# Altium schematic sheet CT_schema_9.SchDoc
size 308 x 210 mm
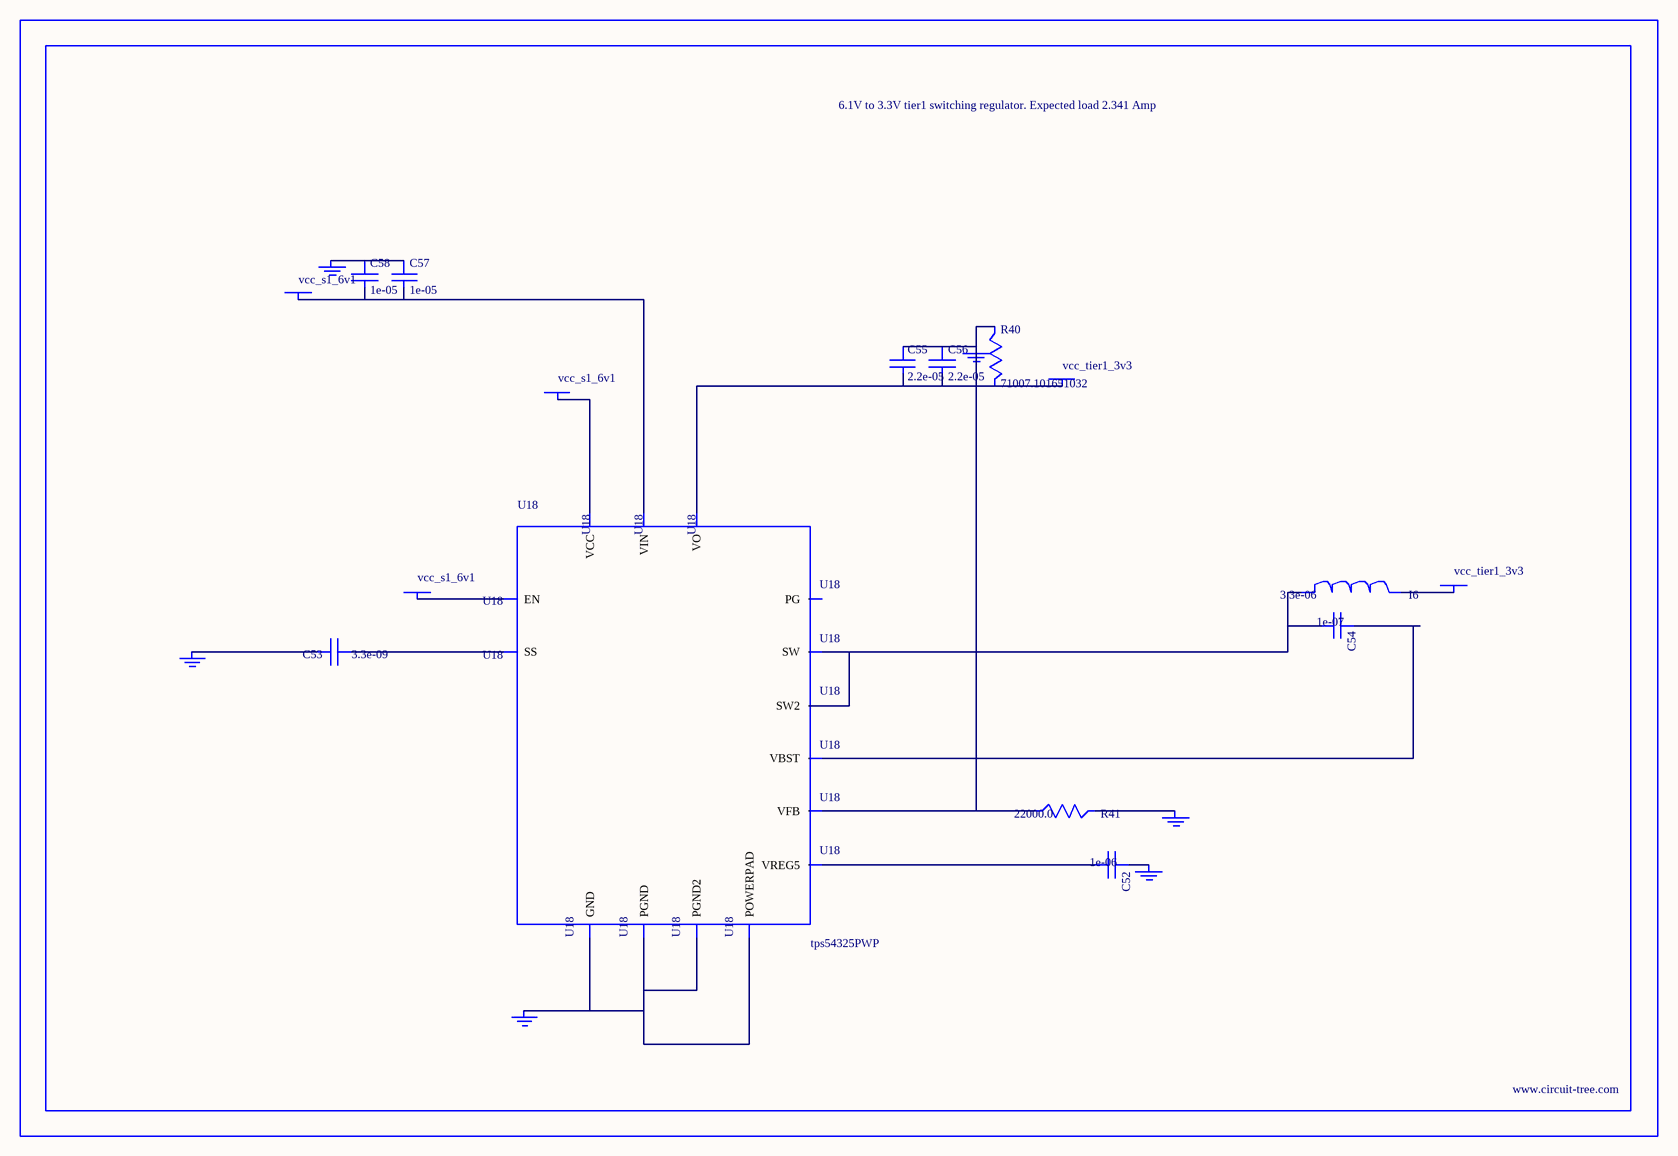
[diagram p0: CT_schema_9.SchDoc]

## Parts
BORDER8  (no value)
C52  1e-06  [C0603]
C53  3.3e-09  [C0402]
C54  1e-07  [C0402]
C55  2.2e-05  [C1210]
C56  2.2e-05  [C1210]
C57  1e-05  [C0805]
C58  1e-05  [C0805]
GND_INSTANCE_8_0  (no value)
GND_INSTANCE_8_1  (no value)
GND_INSTANCE_8_2  (no value)
GND_INSTANCE_8_3  (no value)
GND_INSTANCE_8_4  (no value)
GND_INSTANCE_8_5  (no value)
I6  3.3e-06  [WE-HCI_7030/7040/7050]
POWER_INSTANCE_8_0  vcc_tier1_3v3
POWER_INSTANCE_8_1  vcc_s1_6v1
POWER_INSTANCE_8_2  vcc_tier1_3v3
POWER_INSTANCE_8_3  vcc_s1_6v1
POWER_INSTANCE_8_4  vcc_s1_6v1
R40  71007.101651032  [R0603]
R41  22000.0  [R0603]
U18  tps54325PWP  [HTSSOP14]

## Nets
NetC52_1: C52.1 GND_INSTANCE_8_2.0(GND)
NetC52_2: C52.2 U18.3(VREG5)
NetC53_1: C53.1 U18.4(SS)
NetC53_2: C53.2 GND_INSTANCE_8_3.0(GND)
NetC54_1: C54.1 U18.12(VBST)
NetC54_2: C54.2 I6.1 U18.10(SW) U18.11(SW2)
NetC55_1: C55.1 C56.1 GND_INSTANCE_8_0.0(GND) R40.1 R41.1 U18.2(VFB)
NetC55_2: C55.2 C56.2 POWER_INSTANCE_8_0.0(PWR) R40.2 U18.1(VO)
NetC57_1: C57.1 C58.1 GND_INSTANCE_8_5.0(GND)
NetC57_2: C57.2 C58.2 POWER_INSTANCE_8_3.0(PWR) U18.13(VIN)
NetGND_INSTANCE_8_1_0: GND_INSTANCE_8_1.0(GND) R41.2
NetGND_INSTANCE_8_4_0: GND_INSTANCE_8_4.0(GND) U18.5(GND) U18.8(PGND) U18.9(PGND2) U18.15(POWERPAD)
NetI6_2: I6.2 POWER_INSTANCE_8_2.0(PWR)
NetPOWER_INSTANCE_8_1_0: POWER_INSTANCE_8_1.0(PWR) U18.7(EN)
NetPOWER_INSTANCE_8_4_0: POWER_INSTANCE_8_4.0(PWR) U18.14(VCC)

Not connected (* = marked no-connect by the designer): U18 6(PG)

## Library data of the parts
BORDER8 = BORDER_PAGE8
C52 = C0603C105K3RACTU
C53 = C0402C332K3RAC
C54 = C0402C104K3RACTU
C55 C56 = GRM32ER61E226ME15L
C57 C58 = C0805C106K8RACTU
GND_INSTANCE_8_0-GND_INSTANCE_8_5 = GND
I6 = 744314330
POWER_INSTANCE_8_0-POWER_INSTANCE_8_4 = PWR
R40 = R40
R41 = RC0603JR-0722KL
